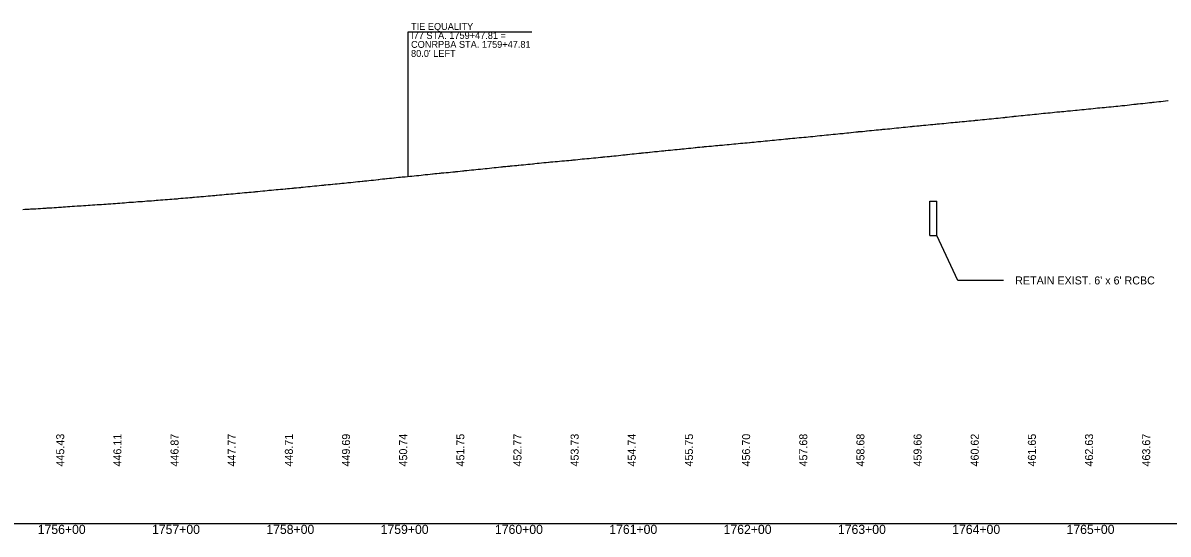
# Model space of a CAD drawing. Extents: x 2017200 to 2047700, y 854850 to 893350.
# Drawn here: x 2030563 to 2031565, y 859091 to 859538 of the extents above; entities that cross this region are included whole.
import ezdxf

# ---------------------------------------------------------------- set-up
doc = ezdxf.new("R2010")
doc.units = 0
for name, color, linetype in [('Culverts', 7, 'Continuous'), ('RD_DDB_Profile_EX', 7, 'Continuous'), ('RD_DDB_Profile_Lbl', 7, 'Continuous'), ('RD_DDB_StaTX', 7, 'Continuous'), ('RD_DDB_StripGrade', 7, 'Continuous'), ('RD_GPK_Profile_Cell', 7, 'Continuous'), ('RD_PD_DR_Pipe_TX', 7, 'Continuous')]:
    doc.layers.add(name, color=color, linetype=linetype)

msp = doc.modelspace()

# ---------------------------------------------------------------- linework, layer by layer
at = {"layer": 'Culverts'}
for p, q in [((2031356.2, 859352.1), (2031356.2, 859382.1)), ((2031356.2, 859382.1), (2031362.2, 859382.1)), ((2031362.2, 859352.1), (2031362.2, 859382.1)), ((2031356.2, 859352.1), (2031362.2, 859352.1))]:
    msp.add_line(p, q, dxfattribs=at)
at = {"layer": 'RD_DDB_Profile_EX'}
for points in [[(2030562.8, 859374.8), (2030564.4, 859374.9), (2030566.4, 859375), (2030568.3, 859375.1), (2030569.5, 859375.2), (2030570.3, 859375.2), (2030572.3, 859375.3), (2030574.3, 859375.4), (2030576.3, 859375.6), (2030578.2, 859375.7), (2030580.2, 859375.8), (2030582.2, 859375.9), (2030583.1, 859376), (2030584.2, 859376.1), (2030586.2, 859376.2), (2030588.2, 859376.3), (2030590.1, 859376.4), (2030592.1, 859376.6), (2030594.1, 859376.7), (2030596.1, 859376.8), (2030596.6, 859376.9), (2030598.1, 859377), (2030600, 859377.2), (2030602, 859377.3), (2030603.4, 859377.3), (2030604, 859377.3), (2030606, 859377.5), (2030608, 859377.6), (2030610.2, 859377.8), (2030611.9, 859377.9), (2030613.9, 859378), (2030615.9, 859378.2), (2030616.9, 859378.2), (2030617.9, 859378.3), (2030619.9, 859378.4), (2030621.8, 859378.6), (2030623.8, 859378.7), (2030625.8, 859378.8), (2030627.8, 859379), (2030629.8, 859379.1), (2030630.5, 859379.2), (2030631.7, 859379.2), (2030633.7, 859379.4), (2030635.7, 859379.5), (2030637.2, 859379.6), (2030637.7, 859379.7), (2030639.7, 859379.8), (2030641.7, 859379.9), (2030643.7, 859380.1), (2030644, 859380.1), (2030645.6, 859380.2), (2030647.6, 859380.4), (2030649.6, 859380.5), (2030650.8, 859380.6), (2030651.6, 859380.7), (2030653.6, 859380.8), (2030655.5, 859381), (2030657.5, 859381.1), (2030659.5, 859381.2), (2030661.5, 859381.4), (2030663.5, 859381.6), (2030664.3, 859381.6), (2030665.4, 859381.7), (2030667.4, 859381.8), (2030669.4, 859382), (2030671.4, 859382.2), (2030673.4, 859382.3), (2030675.4, 859382.4), (2030677.3, 859382.6), (2030677.9, 859382.7), (2030679.3, 859382.8), (2030681.3, 859382.9), (2030683.3, 859383.1), (2030684.6, 859383.2), (2030685.3, 859383.2), (2030687.2, 859383.4), (2030689.2, 859383.5), (2030691.4, 859383.7), (2030693.2, 859383.8), (2030695.2, 859384), (2030697.1, 859384.1), (2030698.2, 859384.2), (2030699.1, 859384.3), (2030701.1, 859384.5), (2030703.1, 859384.7), (2030705.1, 859384.8), (2030707.1, 859385), (2030709, 859385.1), (2030711, 859385.3), (2030711.7, 859385.4), (2030713, 859385.5), (2030715, 859385.7), (2030717, 859385.8), (2030718.5, 859386), (2030718.9, 859386), (2030720.9, 859386.2), (2030722.9, 859386.4), (2030724.9, 859386.6), (2030725.2, 859386.6), (2030726.9, 859386.8), (2030728.8, 859386.9), (2030730.8, 859387.1), (2030732, 859387.2), (2030732.8, 859387.3), (2030734.8, 859387.5), (2030736.8, 859387.6), (2030738.8, 859387.8), (2030740.7, 859388), (2030742.7, 859388.2), (2030744.7, 859388.3), (2030745.6, 859388.4), (2030746.7, 859388.5), (2030748.7, 859388.7), (2030750.6, 859388.9), (2030752.3, 859389.1), (2030752.6, 859389.1), (2030754.6, 859389.3), (2030756.6, 859389.5), (2030758.6, 859389.7), (2030759.1, 859389.7), (2030760.5, 859389.8), (2030762.5, 859390), (2030764.5, 859390.2), (2030765.9, 859390.3), (2030766.5, 859390.4), (2030768.5, 859390.6), (2030770.4, 859390.8), (2030772.6, 859391), (2030774.4, 859391.1), (2030776.4, 859391.3), (2030777.9, 859391.5), (2030778.4, 859391.5), (2030779.4, 859391.6), (2030780.4, 859391.7), (2030782.4, 859391.9), (2030784.3, 859392.1), (2030786.1, 859392.3), (2030788.3, 859392.5), (2030790.3, 859392.6), (2030792.3, 859392.8), (2030792.9, 859392.9), (2030794.2, 859393), (2030796.2, 859393.2), (2030798.2, 859393.4), (2030799.7, 859393.5), (2030800.2, 859393.6), (2030802.2, 859393.8), (2030804.2, 859394), (2030806.1, 859394.1), (2030806.5, 859394.2), (2030808.1, 859394.3), (2030810.1, 859394.5), (2030812.1, 859394.7), (2030813.3, 859394.8), (2030814.1, 859394.9), (2030816, 859395.1), (2030818, 859395.3), (2030820, 859395.5), (2030822, 859395.7), (2030824, 859395.9), (2030826, 859396.1), (2030826.8, 859396.2), (2030827.9, 859396.3), (2030829.9, 859396.5), (2030831.9, 859396.7), (2030833.6, 859396.8), (2030833.9, 859396.9), (2030835.9, 859397.1), (2030837.8, 859397.3), (2030839.8, 859397.5), (2030840.3, 859397.5), (2030841.8, 859397.7), (2030843.8, 859397.9), (2030845.8, 859398.1), (2030847.1, 859398.2), (2030847.8, 859398.2), (2030849.7, 859398.4), (2030851.7, 859398.7), (2030853.9, 859398.9), (2030855.7, 859399.1), (2030857.7, 859399.2), (2030859.6, 859399.5), (2030860.6, 859399.6), (2030861.6, 859399.7), (2030863.6, 859399.9), (2030865.6, 859400.1), (2030867.6, 859400.3), (2030869.6, 859400.5), (2030871.5, 859400.7), (2030873.5, 859400.9), (2030874.2, 859401), (2030875.5, 859401.2), (2030877.5, 859401.4), (2030879.4, 859401.6), (2030881, 859401.8), (2030881.4, 859401.8), (2030883.4, 859402), (2030885.4, 859402.2), (2030887.4, 859402.4), (2030887.7, 859402.5), (2030889.3, 859402.6), (2030891.3, 859402.9), (2030893.3, 859403.1), (2030894.5, 859403.2), (2030895.3, 859403.3), (2030897.3, 859403.4), (2030899.3, 859403.6), (2030901.3, 859403.8), (2030903.2, 859404), (2030905.2, 859404.2), (2030907.2, 859404.4), (2030908, 859404.5), (2030909.2, 859404.6), (2030911.2, 859404.8), (2030913.1, 859405), (2030914.8, 859405.2), (2030915.1, 859405.3), (2030917.1, 859405.4), (2030919.1, 859405.7), (2030921.1, 859405.9), (2030921.6, 859405.9), (2030923.1, 859406.1), (2030925, 859406.2), (2030927, 859406.5), (2030928.3, 859406.6), (2030929, 859406.7), (2030931, 859406.9), (2030933, 859407), (2030935.1, 859407.2), (2030936.9, 859407.4), (2030938.9, 859407.6), (2030940.9, 859407.8), (2030941.5, 859407.9), (2030941.9, 859407.9), (2030943.4, 859408.1), (2030945.4, 859408.2), (2030947.4, 859408.4), (2030948.6, 859408.6), (2030949.4, 859408.7), (2030951.3, 859408.9), (2030953.3, 859409.1), (2030955.4, 859409.3), (2030957.3, 859409.5), (2030959.2, 859409.7), (2030961.2, 859409.9), (2030962.2, 859410), (2030963.2, 859410.1), (2030965.2, 859410.3), (2030967.2, 859410.5), (2030969.1, 859410.7), (2030971.1, 859410.9), (2030973.1, 859411.1), (2030975.1, 859411.4), (2030975.7, 859411.4), (2030977, 859411.5), (2030979, 859411.7), (2030981, 859412), (2030982.5, 859412.1), (2030983, 859412.2), (2030985.2, 859412.4), (2030986.9, 859412.5), (2030988.9, 859412.7), (2030989.3, 859412.8), (2030990.9, 859413), (2030992.9, 859413.1), (2030994.8, 859413.3), (2030996, 859413.4), (2030996.8, 859413.5), (2030998.8, 859413.7), (2031000.8, 859413.9), (2031002.8, 859414.1), (2031004.7, 859414.3), (2031006.7, 859414.5), (2031008.7, 859414.7), (2031009.6, 859414.8), (2031010.7, 859414.9), (2031012.6, 859415.1), (2031014.6, 859415.3), (2031016.6, 859415.5), (2031018.6, 859415.7), (2031020.6, 859415.9), (2031022.5, 859416.1), (2031023.1, 859416.1), (2031024.5, 859416.3), (2031026.5, 859416.5), (2031028.5, 859416.6), (2031029.9, 859416.8), (2031030.4, 859416.8), (2031032.4, 859417), (2031034.4, 859417.2), (2031036.7, 859417.4), (2031038.3, 859417.6), (2031040.3, 859417.7), (2031042.3, 859417.9), (2031043.4, 859418), (2031044.3, 859418.1), (2031046.3, 859418.3), (2031048.2, 859418.5), (2031050.2, 859418.7), (2031052.2, 859418.9), (2031054.2, 859419.1), (2031056.1, 859419.3), (2031057, 859419.3), (2031058.1, 859419.4), (2031060.1, 859419.6), (2031062.1, 859419.9), (2031064.1, 859420), (2031066, 859420.2), (2031068, 859420.4), (2031070, 859420.6), (2031070.5, 859420.7), (2031072, 859420.9), (2031073.9, 859421), (2031075.9, 859421.2), (2031077.3, 859421.4), (2031077.9, 859421.5), (2031079.9, 859421.7), (2031081.8, 859421.8), (2031084, 859422), (2031085.8, 859422.3), (2031087.8, 859422.5), (2031089.8, 859422.6), (2031090.8, 859422.7), (2031091.7, 859422.8), (2031093.7, 859423.1), (2031095.7, 859423.3), (2031097.7, 859423.5), (2031099.6, 859423.7), (2031101.6, 859423.9), (2031103.6, 859424.1), (2031104.4, 859424.2), (2031105.8, 859424.3), (2031107.5, 859424.5), (2031109.5, 859424.7), (2031111.1, 859424.9), (2031111.5, 859424.9), (2031113.5, 859425.1), (2031115.5, 859425.3), (2031117.4, 859425.5), (2031117.9, 859425.5), (2031119.4, 859425.7), (2031121.4, 859425.9), (2031123.4, 859426.1), (2031124.7, 859426.2), (2031125.3, 859426.3), (2031127.3, 859426.5), (2031129.3, 859426.7), (2031131.4, 859426.9), (2031133.2, 859427.1), (2031135.2, 859427.3), (2031137.2, 859427.5), (2031138.2, 859427.6), (2031139.2, 859427.7), (2031141.2, 859427.9), (2031143.1, 859428.1), (2031145.1, 859428.3), (2031147.1, 859428.5), (2031149.1, 859428.7), (2031151, 859428.9), (2031151.7, 859429), (2031153, 859429.1), (2031155, 859429.3), (2031157, 859429.4), (2031158.5, 859429.6), (2031159, 859429.7), (2031160.9, 859429.9), (2031162.9, 859430), (2031164.9, 859430.2), (2031165.3, 859430.2), (2031166.9, 859430.4), (2031168.8, 859430.6), (2031170.8, 859430.8), (2031172.1, 859430.9), (2031172.8, 859430.9), (2031174.8, 859431.1), (2031176.7, 859431.3), (2031178.8, 859431.5), (2031180.7, 859431.6), (2031182.7, 859431.9), (2031184.7, 859432.1), (2031185.6, 859432.2), (2031186.6, 859432.2), (2031188.6, 859432.4), (2031190.6, 859432.6), (2031192.6, 859432.8), (2031194.5, 859433), (2031196.5, 859433.1), (2031198.5, 859433.3), (2031199.1, 859433.4), (2031200.5, 859433.5), (2031202.5, 859433.7), (2031204.4, 859433.9), (2031205.9, 859434.1), (2031206.4, 859434.1), (2031208.4, 859434.3), (2031210.4, 859434.5), (2031212.3, 859434.7), (2031212.7, 859434.7), (2031214.3, 859434.9), (2031216.3, 859435.1), (2031218.3, 859435.3), (2031219.4, 859435.4), (2031220.3, 859435.4), (2031222.2, 859435.6), (2031224.2, 859435.8), (2031226.2, 859436), (2031228.2, 859436.2), (2031230.1, 859436.4), (2031232.1, 859436.6), (2031233, 859436.7), (2031234.1, 859436.8), (2031236.1, 859437), (2031238.1, 859437.2), (2031240, 859437.3), (2031242, 859437.6), (2031244, 859437.7), (2031246, 859437.9), (2031246.5, 859438), (2031247.9, 859438.1), (2031249.9, 859438.4), (2031251.9, 859438.5), (2031253.3, 859438.6), (2031253.9, 859438.7), (2031255.8, 859438.9), (2031257.8, 859439), (2031260.1, 859439.3), (2031261.8, 859439.5), (2031263.8, 859439.7), (2031265.7, 859439.9), (2031266.8, 859440), (2031267.7, 859440.1), (2031269.7, 859440.3), (2031271.7, 859440.5), (2031273.6, 859440.7), (2031275.6, 859440.9), (2031277.6, 859441.1), (2031279.6, 859441.2), (2031280.4, 859441.3), (2031281.6, 859441.5), (2031283.5, 859441.7), (2031285.5, 859441.9), (2031287.1, 859442), (2031287.5, 859442), (2031289.5, 859442.3), (2031291.4, 859442.5), (2031293.4, 859442.7), (2031293.9, 859442.8), (2031295.4, 859442.9), (2031297.4, 859443), (2031299.3, 859443.3), (2031300.7, 859443.5), (2031301.3, 859443.5), (2031303.3, 859443.7), (2031305.3, 859443.9), (2031307.5, 859444.1), (2031309.2, 859444.3), (2031311.2, 859444.4), (2031313.2, 859444.6), (2031314.2, 859444.7), (2031315.2, 859444.9), (2031317.1, 859445), (2031319.1, 859445.2), (2031321.1, 859445.4), (2031323.1, 859445.6), (2031325.1, 859445.8), (2031327, 859446), (2031327.8, 859446.1), (2031329, 859446.2), (2031331, 859446.4), (2031333, 859446.6), (2031334.5, 859446.8), (2031334.9, 859446.8), (2031336.9, 859447), (2031338.9, 859447.2), (2031340.9, 859447.4), (2031341.3, 859447.5), (2031342.8, 859447.6), (2031344.8, 859447.8), (2031346.8, 859448), (2031348.1, 859448.1), (2031348.8, 859448.2), (2031350.8, 859448.4), (2031352.7, 859448.5), (2031354.8, 859448.8), (2031356.7, 859449), (2031358.7, 859449.2), (2031360.6, 859449.3), (2031361.6, 859449.4), (2031362.6, 859449.5), (2031364.6, 859449.7), (2031366.6, 859449.9), (2031368.6, 859450), (2031370.5, 859450.3), (2031372.5, 859450.5), (2031374.5, 859450.7), (2031375.2, 859450.7), (2031376.5, 859450.8), (2031378.4, 859451), (2031380.4, 859451.2), (2031381.9, 859451.4), (2031382.4, 859451.4), (2031384.4, 859451.6), (2031386.4, 859451.7), (2031388.3, 859451.9), (2031388.7, 859452), (2031390.3, 859452.2), (2031392.3, 859452.3), (2031394.3, 859452.5), (2031395.5, 859452.6), (2031396.2, 859452.7), (2031398.2, 859452.9), (2031400.2, 859453.1), (2031402.2, 859453.3), (2031404.1, 859453.5), (2031406.1, 859453.7), (2031408.1, 859453.9), (2031409, 859454), (2031410.1, 859454.1), (2031412.1, 859454.3), (2031414, 859454.5), (2031416, 859454.7), (2031418, 859454.9), (2031420, 859455.1), (2031421.9, 859455.3), (2031422.5, 859455.4), (2031423.9, 859455.6), (2031425.9, 859455.8), (2031427.9, 859456), (2031429.3, 859456.1), (2031429.9, 859456.2), (2031431.8, 859456.3), (2031433.8, 859456.6), (2031436.1, 859456.8), (2031437.8, 859457), (2031439.7, 859457.2), (2031441.7, 859457.4), (2031442.9, 859457.6), (2031443.7, 859457.6), (2031445.7, 859457.8), (2031447.7, 859458), (2031449.6, 859458.2), (2031451.6, 859458.5), (2031453.6, 859458.7), (2031455.6, 859458.9), (2031456.4, 859458.9), (2031457.5, 859459), (2031459.5, 859459.2), (2031461.5, 859459.4), (2031463.5, 859459.6), (2031465.4, 859459.8), (2031467.4, 859460), (2031469.4, 859460.2), (2031469.9, 859460.2), (2031471.4, 859460.4), (2031473.3, 859460.5), (2031475.3, 859460.7), (2031476.7, 859460.9), (2031477.3, 859460.9), (2031479.3, 859461.1), (2031481.3, 859461.3), (2031483.5, 859461.5), (2031485.2, 859461.7), (2031487.2, 859461.9), (2031489.2, 859462.1), (2031490.2, 859462.2), (2031491.1, 859462.3), (2031493.1, 859462.5), (2031495.1, 859462.7), (2031497.1, 859462.9), (2031499.1, 859463.1), (2031501, 859463.3), (2031503, 859463.5), (2031503.8, 859463.6), (2031505, 859463.7), (2031507, 859463.8), (2031508.9, 859464), (2031510.6, 859464.2), (2031510.9, 859464.3), (2031512.9, 859464.4), (2031514.9, 859464.6), (2031516.9, 859464.8), (2031517.3, 859464.9)], [(2031517.3, 859464.9), (2031518.8, 859465), (2031520.8, 859465.2), (2031522.8, 859465.4), (2031524.1, 859465.6), (2031524.8, 859465.6), (2031526.7, 859465.8), (2031528.7, 859466), (2031530.9, 859466.3), (2031532.7, 859466.5), (2031534.7, 859466.7), (2031536.6, 859466.9), (2031537.6, 859467), (2031538.6, 859467.1), (2031540.6, 859467.3), (2031542.6, 859467.5), (2031544.5, 859467.7), (2031546.5, 859468), (2031548.5, 859468.2), (2031550.5, 859468.4), (2031551.2, 859468.5), (2031552.4, 859468.6), (2031554.4, 859468.8), (2031556.4, 859469.1), (2031557.9, 859469.2), (2031558.4, 859469.3), (2031560.4, 859469.5), (2031562.3, 859469.8), (2031564.3, 859470), (2031564.7, 859470)]]:
    msp.add_lwpolyline(points, dxfattribs=at)
at = {"layer": 'RD_DDB_Profile_Lbl'}
msp.add_lwpolyline([(2030900, 859403.7), (2030900, 859530.2), (2031008.2, 859530.2)], dxfattribs=at)
at = {"layer": 'RD_GPK_Profile_Cell'}
msp.add_line((2020500, 859100), (2047700, 859100), dxfattribs=at)
at = {"layer": 'RD_PD_DR_Pipe_TX'}
for p, q in [((2031380.6, 859312.7), (2031362.2, 859352.1)), ((2031420.6, 859312.7), (2031380.6, 859312.7))]:
    msp.add_line(p, q, dxfattribs=at)

# ---------------------------------------------------------------- texts
at = {"layer": 'RD_DDB_Profile_Lbl'}
for s, p in [('TIE EQUALITY', (2030902.4, 859531.8)), ('I77 STA. 1759+47.81 =', (2030902.4, 859523.9)), ('CONRPBA STA. 1759+47.81', (2030902.4, 859516.1)), ("80.0' LEFT", (2030902.4, 859508.2))]:
    msp.add_text(s, height=6, dxfattribs=at).set_placement(p)
at = {"layer": 'RD_DDB_StaTX'}
for s, p in [('1756+00', (2030575.8, 859091)), ('1757+00', (2030675.8, 859091)), ('1758+00', (2030775.8, 859091)), ('1759+00', (2030875.8, 859091)), ('1760+00', (2030975.8, 859091)), ('1761+00', (2031075.8, 859091)), ('1762+00', (2031175.8, 859091)), ('1763+00', (2031275.8, 859091)), ('1764+00', (2031375.8, 859091)), ('1765+00', (2031475.8, 859091))]:
    msp.add_text(s, height=8, dxfattribs=at).set_placement(p)
at = {"layer": 'RD_DDB_StripGrade'}
for s, p in [('445.43', (2030599, 859150)), ('446.11', (2030649, 859150)), ('446.87', (2030699, 859150)), ('447.77', (2030749, 859150)), ('448.71', (2030799, 859150)), ('449.69', (2030849, 859150)), ('450.74', (2030899, 859150)), ('451.75', (2030949, 859150)), ('452.77', (2030999, 859150)), ('453.73', (2031049, 859150)), ('454.74', (2031099, 859150)), ('455.75', (2031149, 859150)), ('456.70', (2031199, 859150)), ('457.68', (2031249, 859150)), ('458.68', (2031299, 859150)), ('459.66', (2031349, 859150)), ('460.62', (2031399, 859150)), ('461.65', (2031449, 859150)), ('462.63', (2031499, 859150)), ('463.67', (2031549, 859150))]:
    msp.add_text(s, height=7, rotation=90, dxfattribs=at).set_placement(p)
at = {"layer": 'RD_PD_DR_Pipe_TX'}
msp.add_text("RETAIN EXIST. 6' x 6' RCBC", height=7, dxfattribs=at).set_placement((2031430.9, 859309.2))

doc.saveas('drawing.dxf')
